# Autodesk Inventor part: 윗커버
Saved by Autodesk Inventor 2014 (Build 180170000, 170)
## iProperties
Created: 2024-08
Part Number: 윗커버
Material: 일반
Document SubType Name: Modeling
Designer: dg
Density: 1 g/cm^3
Appearance: 기본값
Author: dg
Author: jhkim
Creation Date: 2024-08-09
Sending System: Autodesk Inventor 2025
Preprocessor: ST-DEVELOPER v20
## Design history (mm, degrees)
node "윗커버1"
node "솔리드1"
node "기준1"
